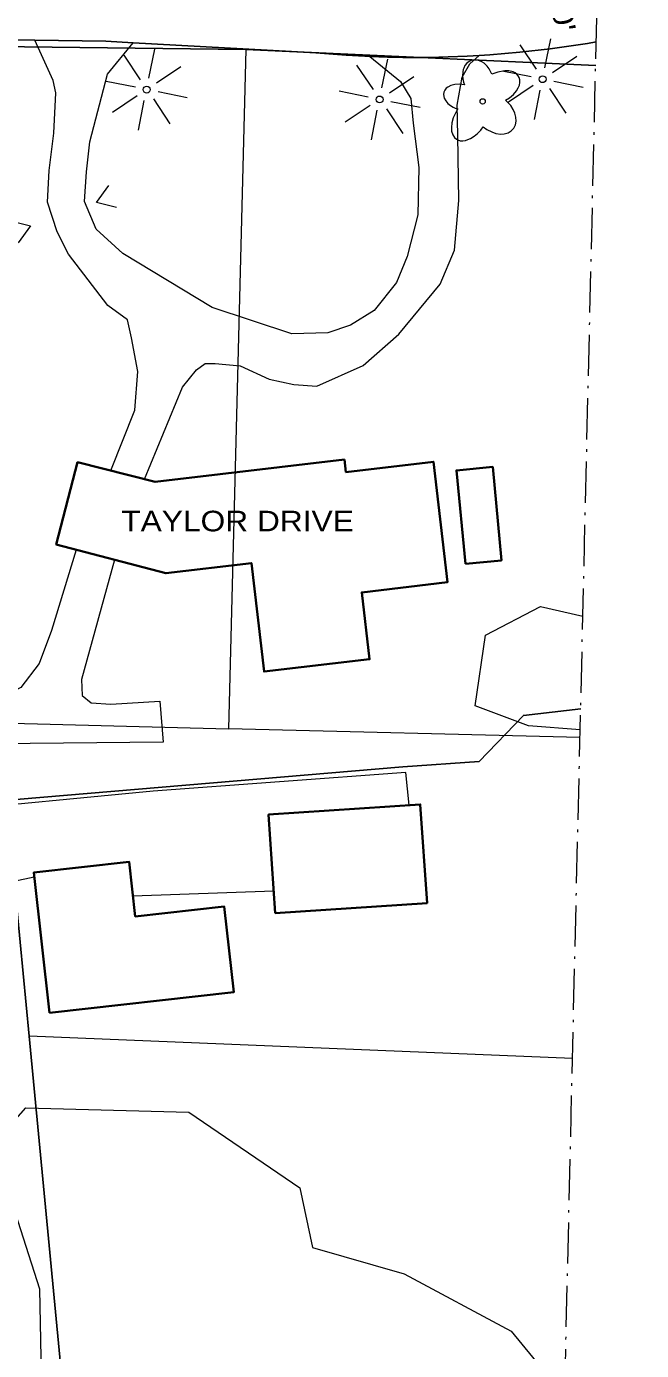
# Model space of a CAD drawing. Extents: x -861682 to -858969, y -1797841 to -1795153.
# Drawn here: x -859153.4 to -858974.4, y -1796143 to -1795757.2 of the extents above; entities that cross this region are included whole.
import ezdxf

# ---------------------------------------------------------------- set-up
doc = ezdxf.new("R2010")
doc.units = 0
doc.header["$LTSCALE"] = 2.4
doc.linetypes.add('DOT_DASHED', pattern=[7.7, 5, -1.2, 0.3, -1.2])
for name, color, linetype, lineweight in [('10', 7, 'Continuous', 25), ('11', 7, 'Continuous', 13), ('12', 7, 'Continuous', 35), ('14', 7, 'Continuous', 25), ('17', 7, 'Continuous', 13), ('18', 7, 'Continuous', 13), ('30', 7, 'Continuous', 13), ('37', 7, 'Continuous', 13), ('42', 7, 'Continuous', 25), ('46', 7, 'Continuous', 13), ('61', 7, 'Continuous', 13)]:
    doc.layers.add(name, color=color, linetype=linetype, lineweight=lineweight)
doc.layers.add('43', color=7, linetype='Continuous')

msp = doc.modelspace()

# ---------------------------------------------------------------- linework, layer by layer
at = {"layer": '10'}
for p, q in [((-859151.007, -1795761.199), (-859168.553, -1795760.895)), ((-859122.324, -1795761.992), (-859069.215, -1795764.877))]:
    msp.add_line(p, q, dxfattribs=at)
for points in [[(-859122.324, -1795761.992), (-859130.308, -1795761.559), (-859151.007, -1795761.199)], [(-859021.636, -1795765.685), (-859018.585, -1795765.503), (-859009.801, -1795764.758), (-859001.042, -1795763.76), (-858990.139, -1795762.159), (-858987.599, -1795761.688)], [(-859053.47, -1795765.957), (-859054.928, -1795765.903), (-859060.428, -1795765.587), (-859069.215, -1795764.877)], [(-859053.47, -1795765.957), (-859048.32, -1795766.151), (-859043.913, -1795766.237), (-859040.607, -1795766.26), (-859039.505, -1795766.26), (-859036.199, -1795766.236), (-859030.691, -1795766.116), (-859025.185, -1795765.897), (-859021.636, -1795765.685)]]:
    msp.add_lwpolyline(points, dxfattribs=at)
at = {"layer": '11'}
msp.add_line((-859122.429, -1796010.539), (-859081.456, -1796009.099), dxfattribs=at)
for points in [[(-859128.901, -1795886.648), (-859121.9, -1795869.057), (-859121.049, -1795857.756), (-859122.814, -1795847.958), (-859124.065, -1795842.757), (-859129.727, -1795838.501), (-859141.218, -1795823.62), (-859144.467, -1795817.076), (-859147.281, -1795808.448), (-859146.828, -1795799.198), (-859145.507, -1795788.275), (-859144.917, -1795776.607), (-859145.627, -1795773.018), (-859151.007, -1795761.199)], [(-859053.47, -1795765.957), (-859044.569, -1795773.272), (-859041.548, -1795778.257), (-859040.865, -1795785.429), (-859039.207, -1795798.348), (-859039.494, -1795812.105), (-859042.605, -1795824.227), (-859045.742, -1795831.85), (-859052.209, -1795839.952), (-859059.097, -1795844.306), (-859065.723, -1795846.531), (-859076.173, -1795846.783), (-859099.353, -1795839.146), (-859125.342, -1795823.408), (-859133.124, -1795816.257), (-859136.535, -1795808.228), (-859135.977, -1795799.616), (-859134.987, -1795790.817), (-859129.868, -1795771.149), (-859122.324, -1795761.992)], [(-859119.048, -1795889.118), (-859108.028, -1795862.358), (-859103.944, -1795857.248), (-859101.453, -1795855.457), (-859098.466, -1795855.45), (-859091.228, -1795856.071), (-859082.769, -1795859.958), (-859075.588, -1795861.594), (-859068.937, -1795862.041), (-859055.387, -1795856.062), (-859045.027, -1795846.845), (-859032.995, -1795832.312), (-859028.884, -1795822.39), (-859027.575, -1795807.952), (-859027.837, -1795788.998), (-859028.042, -1795780.202), (-859026.595, -1795772.027), (-859024.369, -1795768.077), (-859021.636, -1795765.685)], [(-859138.966, -1795909.721), (-859146.102, -1795933.276), (-859149.733, -1795942.803), (-859155.018, -1795949.883), (-859159.831, -1795952.351), (-859165.413, -1795952.878), (-859183.893, -1795954.081), (-859192.373, -1795953.671), (-859195.488, -1795952.759)], [(-859127.758, -1795912.644), (-859137.418, -1795947.471), (-859137.261, -1795952.153), (-859134.574, -1795954.343), (-859128.865, -1795954.666), (-859114.589, -1795953.858), (-859113.648, -1795965.788), (-859171.8, -1795966.396), (-859179.569, -1795965.851), (-859184.024, -1795966.336), (-859191.918, -1795970.065)], [(-859042.087, -1795984.119), (-859043.027, -1795974.565), (-859116.563, -1795980.029), (-859179.237, -1795986.038), (-859181.848, -1795985.61), (-859184.682, -1795982.919), (-859189.628, -1795982.635)], [(-859151.173, -1796005.109), (-859157.125, -1796006.335), (-859175.528, -1796008.666), (-859175.793, -1796023.268), (-859172.173, -1796049.334), (-859172.198, -1796061.561), (-859176.002, -1796064.824), (-859180.121, -1796063.829)]]:
    msp.add_lwpolyline(points, dxfattribs=at)
at = {"layer": '12'}
for points in [[(-859060.862, -1795883.424), (-859115.969, -1795889.89), (-859138.561, -1795884.226), (-859144.745, -1795908.214), (-859112.843, -1795916.533), (-859087.955, -1795913.613), (-859084.248, -1795945.207), (-859053.544, -1795941.605), (-859055.828, -1795922.138), (-859030.884, -1795919.11), (-859034.994, -1795884.078), (-859060.435, -1795887.063)], [(-859025.686, -1795913.772), (-859028.294, -1795886.603), (-859017.716, -1795885.588), (-859015.172, -1795912.789)], [(-859081.015, -1796015.628), (-859036.854, -1796012.646), (-859038.795, -1795983.897), (-859082.956, -1795986.879)], [(-859146.749, -1796044.654), (-859151.322, -1796003.776), (-859123.534, -1796000.667), (-859121.756, -1796016.558), (-859095.872, -1796013.662), (-859093.077, -1796038.649)]]:
    msp.add_lwpolyline(points, close=True, dxfattribs=at)
at = {"layer": '14'}
msp.add_lwpolyline([(-859170.328, -1795983.616), (-859043.88, -1795972.952), (-859021.656, -1795971.399), (-859008.81, -1795958.001), (-858992.126, -1795956.088)], dxfattribs=at)
at = {"layer": '17'}
for p, q in [((-859002.535, -1795769.235), (-859000.809, -1795760.835)), ((-859117.776, -1795772.279), (-859116.05, -1795763.879)), ((-859004.995, -1795769.695), (-859009.785, -1795762.567)), ((-859120.236, -1795772.739), (-859125.026, -1795765.611)), ((-859052.441, -1795775.593), (-859057.231, -1795768.465)), ((-859049.981, -1795775.133), (-859048.255, -1795766.733)), ((-859000.335, -1795770.635), (-858993.239, -1795765.895)), ((-859115.576, -1795773.679), (-859108.48, -1795768.939)), ((-859047.781, -1795776.533), (-859040.685, -1795771.793)), ((-859006.495, -1795771.895), (-859014.957, -1795770.221)), ((-859121.736, -1795774.939), (-859130.198, -1795773.265)), ((-859115.136, -1795776.199), (-859106.656, -1795777.923)), ((-859053.941, -1795777.793), (-859062.403, -1795776.119)), ((-859005.955, -1795774.395), (-859013.181, -1795779.251)), ((-859005.575, -1795784.355), (-859003.895, -1795775.755)), ((-859001.235, -1795775.295), (-858996.435, -1795782.509)), ((-858999.895, -1795773.155), (-858991.415, -1795774.879)), ((-859121.196, -1795777.439), (-859128.422, -1795782.295)), ((-859120.816, -1795787.399), (-859119.136, -1795778.799)), ((-859116.476, -1795778.339), (-859111.676, -1795785.553)), ((-859047.341, -1795779.053), (-859038.861, -1795780.777)), ((-859053.401, -1795780.293), (-859060.627, -1795785.149)), ((-859053.021, -1795790.253), (-859051.341, -1795781.653)), ((-859048.681, -1795781.193), (-859043.881, -1795788.407))]:
    msp.add_line(p, q, dxfattribs=at)
msp.add_lwpolyline([(-859020.475, -1795786.477), (-859019.433, -1795787.245), (-859018.027, -1795787.967), (-859016.779, -1795788.373), (-859015.407, -1795788.569), (-859014.389, -1795788.519), (-859013.245, -1795788.229), (-859012.313, -1795787.677), (-859011.573, -1795786.889), (-859011.105, -1795785.931), (-859010.895, -1795784.853), (-859010.999, -1795783.657), (-859011.289, -1795782.485), (-859011.775, -1795781.425), (-859012.497, -1795780.281), (-859013.363, -1795779.361), (-859014.045, -1795778.749), (-859012.863, -1795778.033), (-859011.717, -1795777.085), (-859010.797, -1795775.993), (-859010.275, -1795775.137), (-859009.943, -1795774.323), (-859009.797, -1795773.507), (-859009.837, -1795772.745), (-859010.053, -1795772.065), (-859010.311, -1795771.613), (-859010.731, -1795771.139), (-859011.191, -1795770.785), (-859011.757, -1795770.495), (-859012.993, -1795770.167), (-859014.235, -1795770.133), (-859016.281, -1795770.509), (-859017.941, -1795771.147), (-859018.731, -1795769.569), (-859019.385, -1795768.755), (-859019.797, -1795768.353), (-859020.261, -1795767.953), (-859020.863, -1795767.561), (-859021.867, -1795767.129), (-859022.881, -1795766.959), (-859023.769, -1795767.059), (-859024.569, -1795767.393), (-859025.235, -1795767.879), (-859025.795, -1795768.585), (-859026.145, -1795769.341), (-859026.303, -1795769.779), (-859026.471, -1795770.455), (-859026.523, -1795771.617), (-859026.451, -1795772.515), (-859026.239, -1795773.477), (-859025.955, -1795774.283), (-859027.397, -1795774.051), (-859028.755, -1795774.101), (-859029.913, -1795774.387), (-859030.801, -1795774.885), (-859031.241, -1795775.229), (-859031.675, -1795775.795), (-859031.913, -1795776.329), (-859032.037, -1795777.007), (-859031.835, -1795778.111), (-859031.379, -1795778.923), (-859030.755, -1795779.685), (-859029.977, -1795780.301), (-859029.279, -1795780.725), (-859028.615, -1795781.013), (-859027.887, -1795781.251), (-859028.571, -1795782.463), (-859029.193, -1795783.831), (-859029.589, -1795785.333), (-859029.723, -1795786.667), (-859029.713, -1795787.757), (-859029.379, -1795788.775), (-859028.857, -1795789.621), (-859028.299, -1795790.057), (-859027.913, -1795790.303), (-859027.179, -1795790.527), (-859026.385, -1795790.539), (-859025.615, -1795790.415), (-859024.955, -1795790.203), (-859024.211, -1795789.881), (-859023.135, -1795789.201), (-859022.173, -1795788.415), (-859021.217, -1795787.397), (-859020.471, -1795786.487)], dxfattribs=at)
for centre, radius in [((-859003.195, -1795772.595), 1), ((-859118.436, -1795775.639), 1), ((-859050.641, -1795778.493), 1), ((-859020.655, -1795779.065), 0.773)]:
    msp.add_circle(centre, radius, dxfattribs=at)
at = {"layer": '18'}
for points in [[(-858992.267, -1795962.144), (-859007.276, -1795961.03), (-859022.793, -1795955.197), (-859019.833, -1795934.563), (-859003.83, -1795926.228), (-858991.497, -1795929.066)], [(-859000.584, -1796200.948), (-859030.413, -1796220.763), (-859061.004, -1796234.175), (-859082.06, -1796236.181), (-859097.001, -1796225.145), (-859115.759, -1796225.664), (-859143.622, -1796221.311), (-859148.513, -1796179.853), (-859149.493, -1796125.159), (-859163.095, -1796083.032), (-859153.599, -1796072.325), (-859106.129, -1796073.572), (-859073.857, -1796095.639), (-859070.132, -1796112.997), (-859043.544, -1796120.651), (-859012.341, -1796137.386), (-858996.789, -1796156.325)]]:
    msp.add_lwpolyline(points, dxfattribs=at)
at = {"layer": '30'}
for p, q in [((-859089.56, -1795763.911), (-859094.584, -1795961.873)), ((-859161.479, -1795960.15), (-859094.584, -1795961.873)), ((-858992.321, -1795964.437), (-859094.584, -1795961.873)), ((-858994.498, -1796057.945), (-859152.648, -1796051.454))]:
    msp.add_line(p, q, dxfattribs=at)
at = {"layer": '37'}
for points in [[(-859127.184, -1795810.018), (-859133.035, -1795808.495), (-859129.467, -1795803.613)], [(-859158.108, -1795813.825), (-859152.257, -1795815.348), (-859155.825, -1795820.23)]]:
    msp.add_lwpolyline(points, dxfattribs=at)
at = {"layer": '42'}
for p, q in [((-859089.56, -1795763.911), (-859190.421, -1795762.699)), ((-858987.76, -1795768.599), (-859089.56, -1795763.911)), ((-859161.479, -1795960.15), (-859152.648, -1796051.454))]:
    msp.add_line(p, q, dxfattribs=at)
msp.add_lwpolyline([(-859152.648, -1796051.454), (-859143.732, -1796144.99), (-859136.702, -1796222.627), (-859130.98, -1796295.086)], dxfattribs=at)
at = {"layer": '61', "linetype": 'DOT_DASHED'}
msp.add_line((-859035.9, -1797835.881), (-858974.429, -1795196.105), dxfattribs=at)

# ---------------------------------------------------------------- texts
at = {"layer": '43', "width": 1.2}
msp.add_text("40'", height=6, rotation=280.081, dxfattribs=at).set_placement((-859001.58, -1795746.798))
at = {"layer": '46', "width": 1.15}
msp.add_text('TAYLOR DRIVE', height=6, dxfattribs=at).set_placement((-859125.828, -1795904.341))

doc.saveas('drawing.dxf')
